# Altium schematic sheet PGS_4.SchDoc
size 381 x 241 mm; SheetNumber: 2; SheetTotal: 2
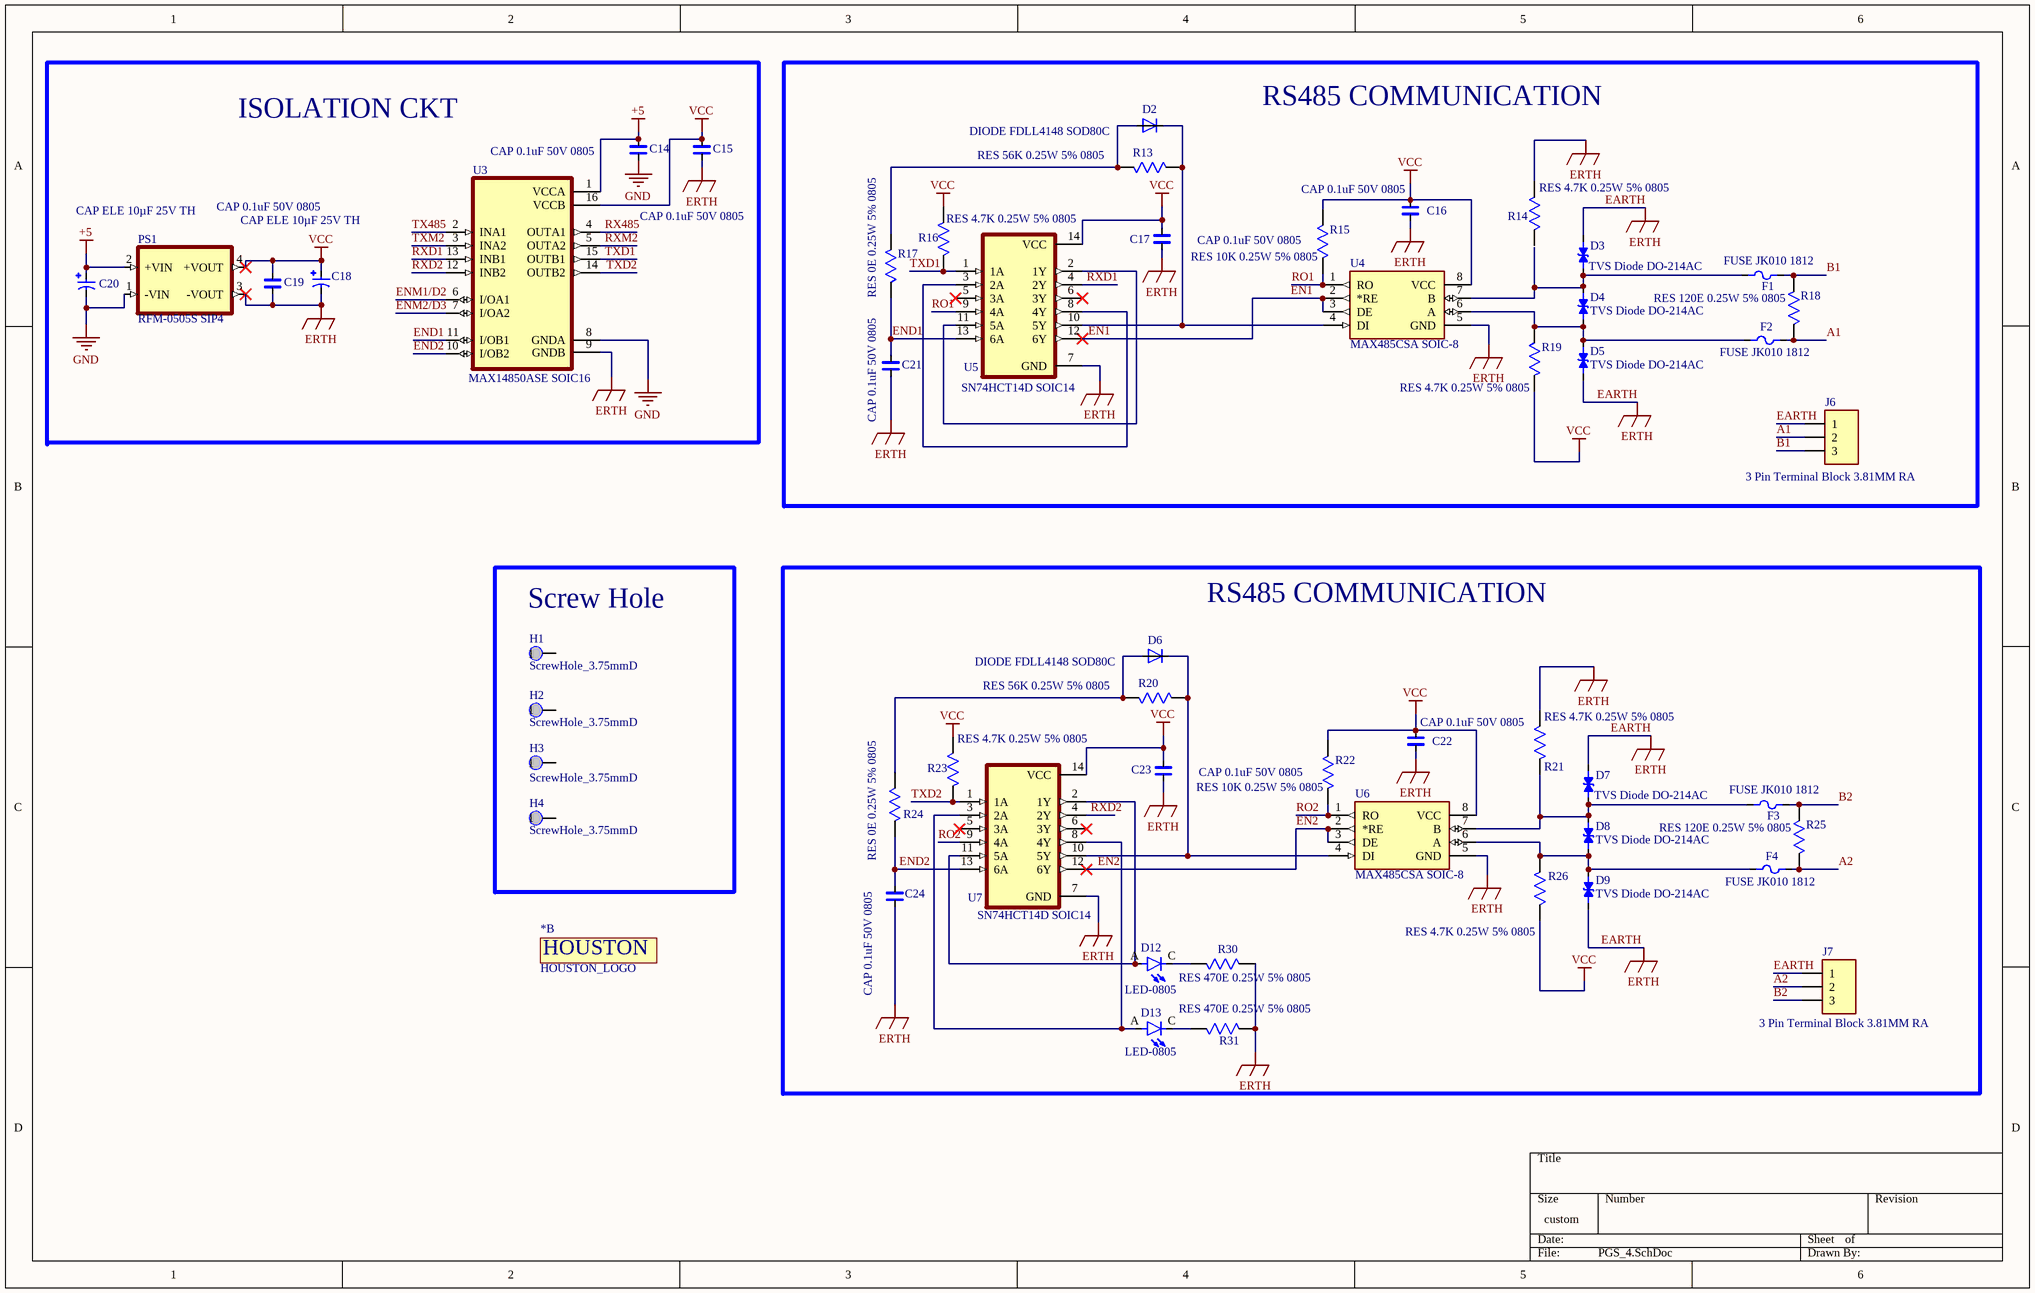
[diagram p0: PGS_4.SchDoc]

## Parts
*  HOUSTON_LOGO  [HOUSTON_LOGO]  (part B of 2)
C14  CAP 0.1uF 50V 0805  [CAP CER 0.1uF/50V 5%]
C15  CAP 0.1uF 50V 0805  [CAP CER 0.1uF/50V 5%]
C16  CAP 0.1uF 50V 0805  [CAP CER 0.1uF/50V 5%]
C17  CAP 0.1uF 50V 0805  [CAP CER 0.1uF/50V 5%]
C18  CAP ELE 10µF 25V TH  [CAP ELE 10µF 25V TH]
C19  CAP 0.1uF 50V 0805  [CAP CER 0.1uF/50V 5%]
C20  CAP ELE 10µF 25V TH  [CAP ELE 10µF 25V TH]
C21  CAP 0.1uF 50V 0805  [CAP CER 0.1uF/50V 5%]
C22  CAP 0.1uF 50V 0805  [CAP CER 0.1uF/50V 5%]
C23  CAP 0.1uF 50V 0805  [CAP CER 0.1uF/50V 5%]
C24  CAP 0.1uF 50V 0805  [CAP CER 0.1uF/50V 5%]
D2  DIODE FDLL4148 SOD80C  [DIODE SOD80C]
D3  TVS Diode DO-214AC  [TVS Diode DO-214AC]
D4  TVS Diode DO-214AC  [TVS Diode DO-214AC]
D5  TVS Diode DO-214AC  [TVS Diode DO-214AC]
D6  DIODE FDLL4148 SOD80C  [DIODE SOD80C]
D7  TVS Diode DO-214AC  [TVS Diode DO-214AC]
D8  TVS Diode DO-214AC  [TVS Diode DO-214AC]
D9  TVS Diode DO-214AC  [TVS Diode DO-214AC]
D12  LED-0805  [LED-0805]
D13  LED-0805  [LED-0805]
F1  FUSE JK010 1812  [FUSE JK010 1812]
F2  FUSE JK010 1812  [FUSE JK010 1812]
F3  FUSE JK010 1812  [FUSE JK010 1812]
F4  FUSE JK010 1812  [FUSE JK010 1812]
H1  ScrewHole_3.75mmD  [ScrewHole_3.75mmD - duplicate]
H2  ScrewHole_3.75mmD  [ScrewHole_3.75mmD - duplicate]
H3  ScrewHole_3.75mmD  [ScrewHole_3.75mmD - duplicate]
H4  ScrewHole_3.75mmD  [ScrewHole_3.75mmD - duplicate]
J6  3 Pin Terminal Block 3.81MM RA  [3 Pin Terminal Block 3.81MM RA]
J7  3 Pin Terminal Block 3.81MM RA  [3 Pin Terminal Block 3.81MM RA]
PS1  RFM-0505S SIP4  [RFM-0505S]
R13  RES 56K 0.25W 5% 0805  [RES 0805 10K/0.25W 5%]
R14  RES 4.7K 0.25W 5% 0805  [RES 0805 10K/0.25W 5%]
R15  RES 10K 0.25W 5% 0805  [RES 0805 10K/0.25W 5%]
R16  RES 4.7K 0.25W 5% 0805  [RES 0805 10K/0.25W 5%]
R17  RES 0E 0.25W 5% 0805  [RES 0805 10K/0.25W 5%]
R18  RES 120E 0.25W 5% 0805  [RES 0805 10K/0.25W 5%]
R19  RES 4.7K 0.25W 5% 0805  [RES 0805 10K/0.25W 5%]
R20  RES 56K 0.25W 5% 0805  [RES 0805 10K/0.25W 5%]
R21  RES 4.7K 0.25W 5% 0805  [RES 0805 10K/0.25W 5%]
R22  RES 10K 0.25W 5% 0805  [RES 0805 10K/0.25W 5%]
R23  RES 4.7K 0.25W 5% 0805  [RES 0805 10K/0.25W 5%]
R24  RES 0E 0.25W 5% 0805  [RES 0805 10K/0.25W 5%]
R25  RES 120E 0.25W 5% 0805  [RES 0805 10K/0.25W 5%]
R26  RES 4.7K 0.25W 5% 0805  [RES 0805 10K/0.25W 5%]
R30  RES 470E 0.25W 5% 0805  [RES 0805 10K/0.25W 5%]
R31  RES 470E 0.25W 5% 0805  [RES 0805 10K/0.25W 5%]
U3  MAX14850ASE SOIC16  [MAX14850ASE]
U4  MAX485CSA SOIC-8  [MAX485CSA]
U5  SN74HCT14D SOIC14  [SN74HCT14D SOIC14]
U6  MAX485CSA SOIC-8  [MAX485CSA]
U7  SN74HCT14D SOIC14  [SN74HCT14D SOIC14]

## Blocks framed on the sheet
ISOLATION CKT: C14 C15 C18-C20 PS1 U3
RS485 COMMUNICATION: C16 C17 C21 D2-D5 F1 F2 J6 R13-R19 U4 U5
Screw Hole: H1-H4
RS485 COMMUNICATION: C22-C24 D6-D9 D12 D13 F3 F4 J7 R20-R26 R30 R31 U6 U7

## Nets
+5: C14.2 C20.P PS1.2(+VIN) U3.1(VCCA)
EARTH: C15.1 C16.1 C17.1 C18.N C19.1 C21.1 C22.1 C23.1 C24.1 D3.2 D5.1 D7.2 D9.1 J6.1 J7.1 PS1.3(-VOUT) R14.2 R21.2 R30.2 R31.2 U3.9(GNDB) U4.5(GND) U5.7(GND) U6.5(GND) U7.7(GND)  [also labelled ERTH]
GND: C14.1 C20.N PS1.1(-VIN) U3.8(GNDA)
VCC: C15.2 C16.2 C17.2 C18.P C19.2 C22.2 C23.2 PS1.4(+VOUT) R15.2 R16.2 R19.1 R22.2 R23.2 R26.1 U3.16(VCCB) U4.8(VCC) U5.14(VCC) U6.8(VCC) U7.14(VCC)
A1: F2.2 J6.2 R18.1
A2: F4.2 J7.2 R25.1
B1: F1.2 J6.3 R18.2
B2: F3.2 J7.3 R25.2
EN1: U4.2(*RE) U4.3(DE) U5.12(6Y)
EN2: U6.2(*RE) U6.3(DE) U7.12(6Y)
END1: C21.2 R17.1 U3.11(I/OB1) U5.13(6A)
END2: C24.2 R24.1 U3.10(I/OB2) U7.13(6A)
ENM1/D2: U3.6(I/OA1)
ENM2/D3: U3.7(I/OA2)
RO1: R15.1 U4.1(RO) U5.9(4A)
RO2: R22.1 U6.1(RO) U7.9(4A)
RX485: U3.4(OUTA1)
RXD1: U3.13(INB1) U5.4(2Y)
RXD2: U3.12(INB2) U7.4(2Y)
RXM2: U3.5(OUTA2)
TX485: U3.2(INA1)
TXD1: R16.1 U3.15(OUTB1) U5.1(1A)
TXD2: R23.1 U3.14(OUTB2) U7.1(1A)
TXM2: U3.3(INA2)
NetD2_1: D2.1(K) R13.1 U4.4(DI) U5.10(5Y)
NetD2_2: D2.2(A) R13.2 R17.2
NetD3_1: D3.1 D4.2 F1.1 U4.7(B)
NetD4_1: D4.1 D5.2 F2.1 R19.2 U4.6(A)
NetD6_1: D6.1(K) R20.1 U6.4(DI) U7.10(5Y)
NetD6_2: D6.2(A) R20.2 R24.2
NetD7_1: D7.1 D8.2 F3.1 R21.1 U6.7(B)
NetD8_1: D8.1 D9.2 F4.1 R26.2 U6.6(A)
NetD12_A: D12.A U7.2(1Y) U7.11(5A)
NetD12_C: D12.C R30.1
NetD13_A: D13.A U7.3(2A) U7.8(4Y)
NetD13_C: D13.C R31.1
NetU5_2: U5.2(1Y) U5.11(5A)
NetU5_3: U5.3(2A) U5.8(4Y)

Not connected (* = marked no-connect by the designer): H1 1; H2 1; H3 1; H4 1; R14 1; U5 5(3A)* 6(3Y)*; U7 5(3A)* 6(3Y)*

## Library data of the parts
C14-C17 C19 C21-C24 = CAP CER 0.1uF/50V 5%: CAP CER 0.1uF/50V  Ceramic Capacitor X7R 0805 (2012 Metric); MF: Samsung; MP: CL21B104KCFNNNE
C18 C20 = CAP ELE 10µF 25V TH: 10µF 25V Aluminum Electrolytic Capacitors Radial Lead Type TH, Dia-5mm, Pitch-2mm ECEA1EN100UI; MF: Panasonic
D2 D6 = DIODE FDLL4148 SOD80C: FDLL4148 Diode Standard 75V 200mA _DC_ Surface Mount LLDS; MiniMelf DIODE SOD80C PMLL4148L; MF: Nexperia USA
D3-D5 D7-D9 = TVS Diode DO-214AC: TVS Diode BiDirectional LittileFuse 1.5SMC6.8CA DO-214AC 6V8C; MP: SMAJ7.5CA
D12 D13 = LED-0805: Red 640nm LED Indication - Discrete 1.85V 0805 (2012 Metric) SMT APT2012SRCPRV; MF: Kingbright
F1-F4 = FUSE JK010 1812: FUSE JK010 Polymeric PTC Resettable Fuse 60V 100 mA 0.8W Ih Surface Mount 1812 (4532 Metric), Concave HUAAN MF-MSMF010-60V; MP: MF-MSMF010-2; MF: Bourns
H1-H4 = ScrewHole_3.75mmD: SCREW HEAD DIA 4.5MM, SREW LEG DIA 3 MM
J6 J7 = 3 Pin Terminal Block 3.81MM RA: 3 Pin Terminal Block HDR 3.81MM THT RA 284513-3; MF: TE Connectivity
PS1 = RFM-0505S: DC-DC Converter/Isolator, SIP4, 1kV unreg, Single Output, 1W, 5V Out, RFM Series ¦ RECOM Power Inc. RFM-0505S
R13-R26 = RES 10K 0.25W 5% 0805: RESISTOR, THICK FILM, 10K, 5%, 0805 0.25W; MP: ERJ-6GEYJ103V; MF: Panasonic Electronic
R30 R31 = RES 10K 0.25W 5% 0805: RESISTOR, THICK FILM, 10K, 5%, 0805 0.25W SMT; MP: ERJ-6GEYJ103V; MF: Panasonic Electronic
U3 = MAX14850ASE+T: MAX14850ASE SOIC16 Six-Channel Digital Isolator; MF: Analog Devices
U4 U6 = MAX485CSA: MAX485CSA-RS-485/RS-422 Transceivers, SOIC-8; MF: Analog Devices; MP: MAX485CSA+
U5 U7 = SN74HCT14D: SN74HCT14D SOIC14 6-ch, 4.5-V to 5.5-V inverters with Schmitt-Trigger inputs; MF: Texas Instruments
